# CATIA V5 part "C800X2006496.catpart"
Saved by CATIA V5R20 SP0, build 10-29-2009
Part number: C800X2006496
Source: Unknown
Property "A": "70"
Property "ARTICLENO": "C800X2006496"
Property "B": "32"
Property "BOMINFO": "C800X2006496"
Property "C": "120"
Property "CA": "C800X2006496"
Property "D1": "120"
Property "DES": "ROTATING EYEBOLT WITH RING Ton 20,0 M64x96"
Property "E": "112"
Property "H": "262"
Property "L": "96"
Property "LINA": "C800X2006496"
Property "NB": "C800X2006496"
Property "NBSYN": "$CODE."
Property "NN": "C800X"
Property "NT": "Rotating eyebolt with ring"
Property "SIZE": "M64"
Property "SUPPLIER": "CF"
Property "SW": "100"
Property "WEIGHT": "10900"
Property "WLL": "20.00"
Bounding box of the stored display mesh (mm): x -67 to 67, y -96 to 293.813, z -60 to 60
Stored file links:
  C:\Users\Utente\Desktop\3D files 800X\C800X2006496.catpart
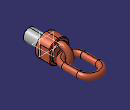
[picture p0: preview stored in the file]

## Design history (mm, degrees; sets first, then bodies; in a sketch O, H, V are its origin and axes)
Body1 "Geometry.1" (main body)
  Solid1 "C800X2006496.catpart": solid without history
